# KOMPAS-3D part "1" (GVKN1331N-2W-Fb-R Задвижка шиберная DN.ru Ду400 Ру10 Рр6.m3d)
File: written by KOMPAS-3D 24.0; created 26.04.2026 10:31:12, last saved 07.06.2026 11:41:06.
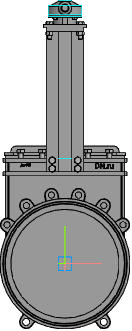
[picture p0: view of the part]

Document properties: Автор: R2D2; Полное имя файла: E:\Работа\Зайцев\АУТСОРС\Даня\GVKN1331N-2W-Fb-R Задвижка шиберная DN.ru Ду400-600 Ру4-6\исходные материалы\DN400\GVKN1331N-2W-Fb-R Задвижка шиберная DN.ru Ду400 Ру10 Рр6.m3d

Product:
- Component [standard]: Hexagon head screw ISO 4017 - М10 x 25  | qty 4  | Масса: 0.026096; Рассекать на разрезах: no; source file: C:\Program Files\ASCON\KOMPAS-3D v24\Libs\PolynomLib\DATA\vault\methods\kompas\3d\PLib_Bolt_1_ISO_1100.m3d
- Body: Тело 4  | qty 1
    Масса: 117.978161
- Body: Тело 5  | qty 1
    Масса: 117.978161
- Body: Тело 6  | qty 1
    Масса: 9.901877
- Body: Тело 7  | qty 1
    Масса: 117.978161
- Body: Тело 8  | qty 1
    Масса: 5.600139
- Body: Тело 12  | qty 1
    Масса: 5.600139
- Component [standard]: (unnamed)  | qty 4  | Масса: 0.1215; Рассекать на разрезах: no; additional columns: М16-6gx55; Болт; ГОСТ 7805-70
- Component [standard]: Гайка М16-6H ГОСТ 5915-70  | qty 4  | Масса: 0.03761; Рассекать на разрезах: no; source file: C:\Program Files\ASCON\KOMPAS-3D v24\Libs\PolynomLib\DATA\vault\methods\kompas\3d\PLib_Nut_OST92_900.m3d
- Component [standard]: Болт М18-6gx30 ГОСТ 7805-70  | qty 1  | Масса: 0.1143; Рассекать на разрезах: no; source file: C:\Program Files\ASCON\KOMPAS-3D v24\Libs\PolynomLib\DATA\vault\methods\kompas\3d\PLib_Bolt_1_900.m3d
- Component [standard]: Болт М18-6gx30 ГОСТ 7805-70  | qty 7  | Масса: 0.1143; Рассекать на разрезах: no
- Component [standard]: Болт М16-6gx30 ГОСТ 7805-70  | qty 1  | Масса: 0.08324; Рассекать на разрезах: no; source file: C:\Program Files\ASCON\KOMPAS-3D v24\Libs\PolynomLib\DATA\vault\methods\kompas\3d\PLib_Bolt_1_900.m3d
- Component [standard]: Болт М16-6gx30 ГОСТ 7805-70  | qty 7  | Масса: 0.08324; Рассекать на разрезах: no
- Body: Тело 14  | qty 1
    Масса: 117.978161
- Part/product: 1
    Масса: 18.2
    Раздел спецификации: Прочие изделия
    Примечание: D050-23732

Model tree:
1. Смещенная плоскость:2
2. Корпус
3. Элемент вращения:1
     Угол 1 = 360
4. Ушко  (with: Ребро.Элемент вращения:1)
5. Элемент выдавливания:5
6. Диск  (with: Ребро.Элемент вращения:1)
7. Элемент выдавливания:3
     Расстояние 1 = 10
8. Скругление:10  (with: Ребро.Элемент выдавливания:5)
     Радиус = 5
9. Скругление:11  (with: Ребро.Элемент выдавливания:5)
     Радиус = 2
10. Массив по концентрической сетке:7  (with: Элемент выдавливания:5, Скругление:10, Скругление:11, Грань.Элемент вращения:1)  (8 pattern instances)
11. Корпус штока
12. Элемент выдавливания:6  (with: Грань.Элемент вращения:1)
     Расстояние 2 = -148
13. Эскиз:3  (with: Грань.Элемент выдавливания:5, Ребро.Скругление:11)
14. Элемент выдавливания:12
15. Массив по концентрической сетке:9  (with: Элемент выдавливания:12, Эскиз:3, Грань.Элемент вращения:1)  (16 pattern instances)
     Шаг 2 = 360
16. Зеркальный массив:2
17. Экземпляр ( 1 )
18. Экземпляр ( 2 )  (with: Массив по концентрической сетке:9, Экземпляр ( 1 ), Элемент выдавливания:12)
19. Экземпляр ( 3 )  (with: Элемент выдавливания:12)
20. Экземпляр ( 4 )  (with: Элемент выдавливания:12)
21. Экземпляр ( 5 )  (with: Элемент выдавливания:12)
22. Экземпляр ( 6 )  (with: Элемент выдавливания:12)
23. Экземпляр ( 7 )  (with: Элемент выдавливания:12)
24. Экземпляр ( 8 )  (with: Элемент выдавливания:12)
25. Экземпляр ( 9 )  (with: Элемент выдавливания:12)
26. Экземпляр ( 10 )  (with: Элемент выдавливания:12)
27. Экземпляр ( 11 )  (with: Элемент выдавливания:12)
28. Экземпляр ( 12 )  (with: Элемент выдавливания:12)
29. Экземпляр ( 13 )  (with: Элемент выдавливания:12)
30. Экземпляр ( 14 )  (with: Элемент выдавливания:12)
31. Экземпляр ( 15 )  (with: Элемент выдавливания:12)
32. Экземпляр ( 16 )  (with: Элемент выдавливания:12)
33. Эскиз:24  (with: Грань.Элемент вращения:1, Ребро.Элемент вращения:1)
34. Элемент выдавливания:36
     Расстояние 2 = 2
35. Зеркальный массив:4  (with: Экземпляр ( 1 ), Экземпляр ( 2 ), Элемент выдавливания:36)
36. Резиновое уплотнение
37. Элемент выдавливания:4
38. Скругление:2  (with: Грань.Элемент выдавливания:4)
     Радиус = 2
39. Скругление:4  (with: Ребро.Элемент выдавливания:6)
     Радиус = 2
40. фланец  (with: Грань.Элемент выдавливания:6, Ребро.Элемент выдавливания:6)
41. Элемент выдавливания:13
     Расстояние 2 = 15
42. Скругление:12  (with: Ребро.Элемент выдавливания:13)
     Радиус = 10
43. Массив по сетке:1  (with: Элемент выдавливания:13, Эскиз:4, Скругление:12)  (2 pattern instances)
     Шаг 1 = 50; Угол раствора = 90
44. Эскиз:5  (with: Грань.Элемент выдавливания:6, Ребро.Элемент выдавливания:13)  (labels: Ребро.Элемент выдавливания:13.Экземпляр ( 2, 1 ))
45. Элемент выдавливания:14  (with: Грань.Элемент вращения:1)
     Расстояние 1 = 21; Смещение 1 = 1
46. Эскиз:6  (with: Грань.Элемент выдавливания:6, Ребро.Элемент выдавливания:13, Ребро.Элемент выдавливания:14)  (labels: Ребро.Элемент выдавливания:13.Экземпляр ( 2, 1 ))
47. Элемент выдавливания:15  (with: Грань.Элемент вращения:1)
     Расстояние 1 = 21; Смещение 1 = 1
48. Эскиз:7  (with: Вершина.Элемент выдавливания:14, Ребро.Элемент выдавливания:14)  (labels: Грань.Элемент выдавливания:13.Экземпляр ( 2, 1 ))
49. Элемент выдавливания:16
50. Эскиз:8  (with: Ребро.Элемент выдавливания:15)  (labels: Грань.Элемент выдавливания:13.Экземпляр ( 2, 1 ))
51. Элемент выдавливания:17  (with: Грань.Элемент выдавливания:16)
     Расстояние 1 = 532
52. Смещенная плоскость:3
53. Эскиз:9  (with: Грань.Элемент выдавливания:16, Вершина.Элемент выдавливания:17, Ребро.Элемент выдавливания:16, Ребро.Элемент выдавливания:17)
54. Элемент выдавливания:18
     Расстояние 2 = 15
55. Скругление:13  (with: Ребро.Элемент выдавливания:16, Ребро.Элемент выдавливания:17)
     Радиус = 15
56. Эскиз:10  (with: Грань.Элемент выдавливания:18, Ребро.Скругление:13, Ребро.Элемент выдавливания:18, Ребро.Элемент выдавливания:17)
57. Элемент выдавливания:19
     Расстояние 1 = 10
58. Эскиз:11  (with: Грань.Элемент выдавливания:13, Ребро.Элемент выдавливания:13)
59. Элемент выдавливания:20
     Расстояние 1 = 10
60. Эскиз:12  (with: Грань.Элемент выдавливания:20, Ребро.Элемент выдавливания:13, Ребро.Элемент выдавливания:17, Вершина.Элемент выдавливания:17, Вершина.Элемент выдавливания:18)
61. Элемент выдавливания:21
     Расстояние 1 = 10
62. Фаска:1  (with: Ребро.Элемент выдавливания:21)
     Угол = 60; Длина 1 = 20; Длина 2 = 34.641
63. Фаска:2  (with: Ребро.Элемент выдавливания:21)
     Угол = 60; Длина 1 = 20; Длина 2 = 34.641
64. Эскиз:13  (with: Грань.Элемент выдавливания:13)
65. Элемент выдавливания:22  (with: Грань.Элемент выдавливания:21)
     Расстояние 1 = 45; Смещение 1 = 25
66. Скругление:14  (with: Ребро.Элемент выдавливания:22)
     Радиус = 20
67. Эскиз:14  (with: Грань.Элемент выдавливания:21, Ребро.Элемент выдавливания:22, Ребро.Элемент выдавливания:21)
68. Элемент выдавливания:23
     Расстояние 1 = 30
69. Эскиз:15  (with: Грань.Элемент выдавливания:23, Ребро.Элемент выдавливания:23)
70. Элемент выдавливания:24  (with: Грань.Элемент выдавливания:19)
     Расстояние 1 = 432
71. Эскиз:16  (with: Грань.Элемент выдавливания:19, Ребро.Элемент выдавливания:24)
72. Элемент выдавливания:25  (with: Грань.Элемент выдавливания:18)
     Расстояние 2 = 25
73. Массив по концентрической сетке:10  (with: Элемент выдавливания:25, Эскиз:16, Грань.Элемент выдавливания:24)  (4 pattern instances)
     Шаг 2 = 360
74. Эскиз:17  (with: Грань.Элемент выдавливания:19, Ребро.Элемент выдавливания:24, Ребро.Элемент выдавливания:19)
75. Элемент выдавливания:26
     Расстояние 1 = 25
76. ИСО фланец  (with: Грань.Элемент выдавливания:26, Ребро.Элемент выдавливания:26)
77. Элемент выдавливания:7
     Расстояние 1 = 10
78. отв. исо фланца  (with: Грань.Элемент выдавливания:7, Ребро.Элемент выдавливания:7)
79. Элемент выдавливания:27  (with: Грань.Элемент выдавливания:7)
     Расстояние 2 = 10
80. Массив по концентрической сетке:11  (with: Элемент выдавливания:27, Грань.Элемент выдавливания:7)  (4 pattern instances)
     Шаг 2 = 360
81. Эскиз:18  (with: Грань.Элемент выдавливания:7, Ребро.Элемент выдавливания:7)
82. Элемент выдавливания:28
     Расстояние 1 = 2
83. Смещенная плоскость:4  (with: Грань.Элемент выдавливания:7)
     Расстояние = 0.5
84. Эскиз:19  (with: Ребро.Элемент выдавливания:7)
85. Элемент выдавливания:29
     Расстояние 1 = 30
86. Эскиз:20  (with: Ребро.Элемент выдавливания:29)
87. Элемент выдавливания:30
     Расстояние 2 = 5
88. Элемент по сечениям:1  (with: Грань.Элемент выдавливания:30, Грань.Элемент выдавливания:29)
89. Скругление:15  (with: Ребро.Элемент выдавливания:30)
     Радиус = 5
90. ЛЕЙБЛ  (with: Ребро.Элемент выдавливания:16, Ребро.Скругление:4)
91. Элемент выдавливания:31  (with: Грань.Элемент выдавливания:6)
     Расстояние 1 = 26; Смещение 1 = 1
92. Нормальная плоскость:1  (with: Грань.Элемент выдавливания:29)
93. Эскиз:21
94. Элемент выдавливания:32
     Расстояние 1 = 100
95. Фаска:3  (with: Ребро.Элемент выдавливания:32)
     Угол = 45; Длина 1 = 10; Длина 2 = 10
96. Эскиз:22  (with: Грань.Элемент выдавливания:32, Ребро.Фаска:3)
97. Элемент выдавливания:33
     Расстояние 1 = 20
98. Массив по концентрической сетке:2  (with: Грань.Элемент выдавливания:7)  (4 pattern instances)
     Шаг 2 = 360
99. Массив по концентрической сетке:3  (with: Грань.Элемент выдавливания:26)  (4 pattern instances)
     Шаг 2 = 360
100. Эскиз:23  (with: Грань.Элемент выдавливания:16, Ребро.Элемент выдавливания:16)
101. Элемент выдавливания:34
102. Зеркальный массив:3  (with: Экземпляр ( 1 ), Экземпляр ( 2 ), Элемент выдавливания:34)
103. Эскиз:25  (labels: Грань.Элемент выдавливания:12.Экземпляр ( 1, 11 ); Ребро.Элемент выдавливания:12.Экземпляр ( 1, 11 ); Ребро.Элемент выдавливания:12.Экземпляр ( 1, 8 ))
104. Элемент выдавливания:37  (with: Грань.Элемент выдавливания:7, Грань.Элемент выдавливания:19, Грань.Элемент выдавливания:18, Грань.Элемент выдавливания:21, Грань.Элемент выдавливания:16, Грань.Элемент выдавливания:34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)  (labels: Ребро.Элемент выдавливания:27.Экземпляр ( 1, 4 ); Грань.Элемент выдавливания:25.Экземпляр ( 1, 2 ); Грань.Элемент выдавливания:34.Экземпляр ( 2 ))
     Расстояние 1 = 126.5

Expressions: v30-20; v161-20; D2-5; D/2-D1/2; L/2+5; 360/n/2; D1*0.85; id3-id4*2; DS*2; D1/4+10; H1-H1/2.5-50; H1/2.5
Referenced files in C:\Program Files\ASCON\KOMPAS-3D v24\Libs\PolynomLib\DATA\vault\Methods\Kompas\3D\: PLib_Bolt_1_ISO_1100.m3d, PLib_Bolt_1_900.m3d, PLib_Nut_OST92_900.m3d
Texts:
  BOSimple***PART:f114febc-ab7b-6638-bb5e-15f0e2e47160***SHORTLOC:A259_7B16EF33AB1642D2[16;1,5;25;10;-;Undefined]
  BOSimple***PART:d5043757-7383-cfe0-2773-bdcfb0c19ea2***SHORTLOC:Root±30±20±10±80±10±©{}30±©{BASE}130±30[Нет;Без покрытия;Без указания материала;55;16;24;2;-]
  BOSimple***PART:17b45fe1-43c8-f41a-5df4-ae57481e6c3b***SHORTLOC:Root±30±10±20±©{}110±10±50±60[Нет;Без покрытия;Без указания материала;-;16;2;24]
  BOSimple***PART:58fea51c-4c27-65e8-868c-b0420730e5b8***SHORTLOC:Root±30±20±10±80±10±©{}30±©{BASE}130±30[Нет;Без покрытия;Без указания материала;30;18;27;2,5;-]
  BOSimple***PART:296a4829-a4b6-4e05-4821-ac6adc08aeaf***SHORTLOC:Root±30±20±10±80±10±©{}30±©{BASE}130±30[Нет;Без покрытия;Без указания материала;30;16;24;2;-]
  GOST 26.020 Pr3
  var3D
  ширина затвора по металлу
  Диаметр исо фланца
  id4
  Диуметр отверстия  исо фланца
  id3
  ось отв. исо фланца
  id5
  ds1
  Hexagon head screw ISO 4017 - М10 x 25 (1)
  hole1
  hole2
  Деталь (1)
  Гайка М16-6H ГОСТ 5915-70 (1)
  bcut1
  hcut1
  cut1
  Болт М18-6gx30 ГОСТ 7805-70 (1)
  Болт М18-6gx30 ГОСТ 7805-70 (2)
  Болт М18-6gx30 ГОСТ 7805-70 (3)
  Болт М18-6gx30 ГОСТ 7805-70 (4)
  Болт М18-6gx30 ГОСТ 7805-70 (5)
  Болт М18-6gx30 ГОСТ 7805-70 (6)
  Болт М18-6gx30 ГОСТ 7805-70 (7)
  Болт М18-6gx30 ГОСТ 7805-70 (8)
  Болт М16-6gx30 ГОСТ 7805-70 (1)
  Болт М16-6gx30 ГОСТ 7805-70 (2)
  Болт М16-6gx30 ГОСТ 7805-70 (3)
  Болт М16-6gx30 ГОСТ 7805-70 (4)
  Болт М16-6gx30 ГОСТ 7805-70 (5)
  Болт М16-6gx30 ГОСТ 7805-70 (6)
  Болт М16-6gx30 ГОСТ 7805-70 (7)
  Болт М16-6gx30 ГОСТ 7805-70 (8)
  Plane. Начало координат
